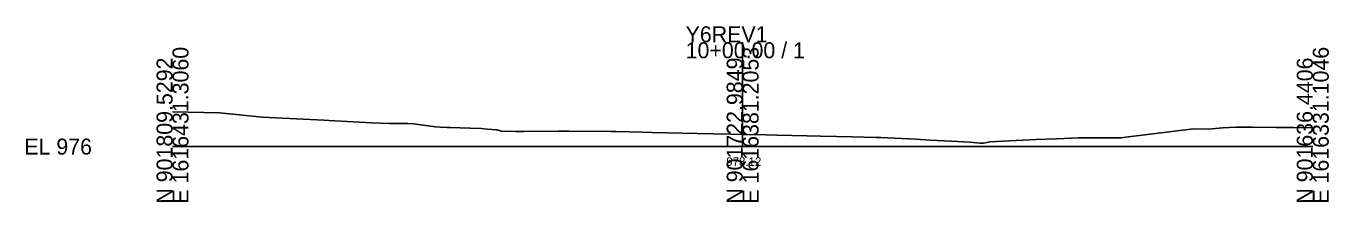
# Model space of a CAD drawing. Extents: x -26 to 203, y -10 to 2517.
# Drawn here: x -25.7 to 202.8, y -9.7 to 21.1 of the extents above; entities that cross this region are included whole.
import ezdxf

# ---------------------------------------------------------------- set-up
doc = ezdxf.new("R2010")
doc.units = 0
for name, color, linetype in [('Exist Cross Section Cell', 7, 'Continuous'), ('Exist XS Center Line Elevation Label', 7, 'Continuous'), ('Exist XS Ground Line', 7, 'Continuous')]:
    doc.layers.add(name, color=color, linetype=linetype)

msp = doc.modelspace()

# ---------------------------------------------------------------- linework, layer by layer
at = {"layer": 'Exist Cross Section Cell'}
for p, q in [((100, 0), (100, 18.28)), ((0, 0), (100, 0)), ((100, 0), (200, 0))]:
    msp.add_line(p, q, dxfattribs=at)
at = {"layer": 'Exist XS Ground Line'}
msp.add_lwpolyline([(0, 6.09), (8.25, 5.91), (15.78, 5.13), (26.54, 4.63), (27.41, 4.6), (30.65, 4.4), (34.96, 4.18), (38.06, 4.07), (41.3, 4.04), (42.28, 3.98), (46.13, 3.49), (47.03, 3.4), (48.15, 3.36), (48.68, 3.34), (50.45, 3.28), (52.19, 3.23), (54.18, 3.16), (55.19, 3.07), (56.91, 2.91), (57.69, 2.69), (60.13, 2.65), (60.51, 2.65), (60.89, 2.65), (61.57, 2.65), (67.72, 2.68), (68.83, 2.69), (69.53, 2.7), (76.83, 2.67), (77.81, 2.64), (82.44, 2.55), (84.05, 2.49), (89.36, 2.38), (92.02, 2.3), (94.81, 2.24), (97.86, 2.18), (100, 2.12), (100.32, 2.12), (104.07, 2.04), (106, 1.99), (111.23, 1.88), (113.67, 1.83), (119.27, 1.7), (123.42, 1.61), (124.25, 1.57), (130.35, 1.3), (132.89, 1.15), (136.57, 0.96), (139.86, 0.75), (141.67, 0.63), (142.26, 0.61), (143.34, 0.83), (151.41, 1.22), (155.09, 1.38), (158.9, 1.54), (161.89, 1.55), (166.06, 1.54), (166.42, 1.56), (167.23, 1.63), (179.1, 3.14), (181.63, 3.03), (184.24, 3.31), (186.55, 3.39), (187.81, 3.43), (189.36, 3.41), (193.61, 3.36), (196.14, 3.33), (196.7, 3.33), (200, 3.26)], dxfattribs=at)

# ---------------------------------------------------------------- texts
at = {"layer": 'Exist Cross Section Cell'}
for s, p in [('Y6REV1', (90, 18.28)), ('10+00.00 / 1', (90, 15.48)), ('EL 976', (-26, -1.4))]:
    msp.add_text(s, height=2.8, dxfattribs=at).set_placement(p)
for s, p in [('E 1616431.3060', (2.8, -10)), ('E 1616381.2053', (102.8, -10)), ('E 1616331.1046', (202.8, -10)), ('N 901809.5292', (0, -10)), ('N 901722.9849', (100, -10)), ('N 901636.4406', (200, -10))]:
    msp.add_text(s, height=2.8, rotation=90, dxfattribs=at).set_placement(p)
at = {"layer": 'Exist XS Center Line Elevation Label'}
msp.add_text('978.12', height=1.5, dxfattribs=at).set_placement((97.14, -3.38))

doc.saveas('drawing.dxf')
